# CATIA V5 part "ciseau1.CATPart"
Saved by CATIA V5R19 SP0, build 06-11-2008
Part number: ciseau1
Publications: "D-vis/goupille1"
Bounding box of the stored display mesh (mm): x -136.374 to 15.617, y -131.102 to 16.061, z 0 to 10
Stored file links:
  C:\Documents and Settings\alenoir\Bureau\mécanisme\ciseau1.CATPart
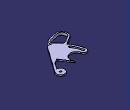
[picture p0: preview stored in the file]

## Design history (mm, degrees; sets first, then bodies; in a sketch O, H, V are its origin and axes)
Parameters
  `D-vis/goupille1` = 30 mm
  LENGTH = 0 mm
Body1 (main body)
  Sketch1 on xy-plane, origin (0.6173, 1.0615, 0), H (0.5482, -0.8363, 0), V (0.8363, 0.5482, 0)
    line L1 (13.9342, 5.5533) -> (55.2099, -98.0146)
    point P1 (16.1474, 0)
    point P2 (0, 200)
    circle A1 centre (0, 0) radius 4
    arc A2 centre (0, 0) radius 125 from (-42.7525, -117.4616) to (9, -124.6756) ccw
    arc A3 centre (42.6692, -103.0126) radius 13.5 from (47.8354, -115.4849) to (55.2099, -98.0146) ccw
    point P4 (47.8354, -115.4849)
    point P8 (0, -30)
    point P9 (0, -22.5)
    arc A4 centre (-27.3616, -75.1754) radius 22.3607 from (-35.0094, -96.1876) to (-27.3616, -52.8147) ccw
    point P10 (-27.3616, -75.1754)
    arc A5 centre (0, 0) radius 15 from (13.9342, 5.5533) to (12.1291, -8.8252) ccw
    line L2 (12.1291, -8.8252) -> (22.1252, -33.907)
    point P13 (22.1252, -52.8147)
    line L3 (-27.3616, -52.8147) -> (22.1252, -52.8147)
    line L4 (22.1252, -52.8147) -> (22.1252, -49.8147)
    line L5 (22.1252, -49.8147) -> (17.1252, -49.8147)
    point P16 (17.1252, -49.8147)
    line L6 (17.1252, -49.8147) -> (22.1252, -47.4832)
    point P17 (22.1252, -47.4832)
    line L7 (22.1252, -47.4832) -> (22.1252, -33.907)
    point P18 (-35.0094, -96.1876)
    spline S1 through (47.8354, -115.4849) (59.6421, -124.3692) (58.5484, -140.7762) (54.1733, -153.5372) (48.7044, -165.9336) (39.5897, -177.6008) (22.8186, -177.9654) (9, -165.7037)
    line L8 (9, -165.7037) -> (9, -124.6756)
    point P19 (9, -165.7037)
    construction line L9 (0, 0) -> (-27.3616, -75.1754)
    arc A6 centre (-38.881, -106.8246) radius 11.3197 from (-42.7525, -117.4616) to (-35.0094, -96.1876) cw
    point P22 (-49.6377, -103.2994)
    construction line L10 (-49.6377, -103.2994) -> (-14.2541, 4.6713)
    point P23 (-14.2541, 4.6713)
    construction line L11 (0, 0) -> (-38.881, -106.8246)
    construction line L12 (0, 0) -> (42.6692, -103.0126)
    axis line L13 (0, 0) -> (0, -125)
    point P24 (0, -125)
    point P25 (47.8354, -115.4849)
    point P26 (9, -165.7037)
    radius A1 = 4
    radius A2 = 125
    radius A3 = 13.5
    radius A4 = 22.3607
    distance P10 O = 80
    distance L2 L1 = 7
    distance P16 L4 = 5
    angle L6 L5 = 25
    distance P13 L1 = 14
    distance L5 L3 = 3
    radius A5 = 15
    angle L13 L12 = 22.5
    angle L11 L13 = 20
    distance L8 L13 = 9
    length L8 = 41.0281
    coincidence: P1 L1, P1 H, P17 L4, L4 L7, P25 P4, P26 P19, A6 P22, P23 A5, P24 A2, P18 L11, P25 L12
    tangency: A3 L1, A3 A2, A5 L1, A4 L3, A6 A2, A6 A4, L10 A5, L10 A6
    horizontal: L3 H
    vertical: L8 V, L13 V, L7 V, L4 V
  Pad1: profile Sketch1, direction (0, 0, 1), length 10
  Sketch2 on start face of Pad1, origin (0.6173, 1.0615, 0), H (0.5482, -0.8363, 0), V (0.8363, 0.5482, 0)
    spline S1 through (14.4994, -165.2858) (23.5036, -173.1647) (37.7673, -172.7797) (45.1958, -161.5242) (49.6979, -150.2687) (53.5247, -137.6625) (54.6502, -125.2814) (44.9707, -121.4545)
    spline S2 through (14.4994, -135.8616) (17.0577, -129.1082) (27.4125, -125.0563)
    line L1 (14.4994, -165.2858) -> (14.4994, -135.8616)
    point P1 (14.4994, -165.2858)
    point P2 (14.4994, -135.8616)
    line L2 (27.4125, -125.0563) -> (44.9707, -121.4545)
    point P3 (27.4125, -125.0563)
    point P4 (44.9707, -121.4545)
    point P5 (14.4994, -165.2858)
    point P6 (14.4994, -135.8616)
    point P7 (27.4125, -125.0563)
    point P8 (44.9707, -121.4545)
    coincidence: P5 P1, P6 P2, P7 P3, P8 P4
    vertical: L1 V
  Pocket1: profile Sketch2, direction (0, 0, 1), through (limit type 6)
  Sketch3 on end face of Pad1, origin (0.6173, 1.0615, 10), H (0.5482, -0.8363, 0), V (0.8363, 0.5482, 0)
    construction arc A1 centre (0, 0) radius 115 from (-39.3323, -108.0647) to (0, -115) ccw
    point P1 (0, -115)
    arc A2 centre (-39.3323, -108.0647) radius 3 from (-40.3584, -110.8837) to (-38.3063, -105.2456) cw
    arc A3 centre (0, -115) radius 3 from (0, -112) to (0, -118) cw
    arc A4 centre (0, 0) radius 112 from (-38.3063, -105.2456) to (0, -112) ccw
    arc A5 centre (0, 0) radius 118 from (0, -118) to (-40.3584, -110.8837) cw
    construction line L1 (0, 0) -> (0, -135.9749)
    point P7 (0, 0)
    axis line L2 (0, 0) -> (-39.3323, -108.0647)
    radius A3 = 3
    radius A1 = 115
    angle L2 L1 = 20
    coincidence: P1 V, P7 V, P7 O
    tangency: A4 A3, A3 A5, A5 A2, A2 A4
    concentricity: A4 O, A5 O
    vertical: L1 V
  Pocket2: profile Sketch3, direction (0, 0, -1), through (limit type 6)
  Sketch4 on start face of Pad1, origin (0.6173, 1.0615, 0), H (0.5482, -0.8363, 0), V (0.8363, 0.5482, 0)
  Sketch5 on start face of Pad1, origin (0.6173, 1.0615, 0), H (0.5482, -0.8363, 0), V (0.8363, 0.5482, 0)
    circle A1 centre (0, 0) radius 125.2848
  Pocket3: profile Sketch5, direction (0, 0, 1), length 5
  Sketch6 on start face of Pad1, origin (0.6173, 1.0615, 0), H (0.5482, -0.8363, 0), V (0.8363, 0.5482, 0)
    circle A1 centre (0, 0) radius 125.3191
  Pocket4: profile Sketch6, direction (0, 0, 1), length 5
  Plane1: stored without definition
  Sketch7 on end face of Pad1, origin (0, 0, 10), H (1, 0, 0), V (0, 1, 0)
    circle A1 centre (0.6173, 1.0615) radius 15
    reference projected arc E1 centre (0.6173, 1.0615) radius 15 from (12.9008, -7.5475) to (-0.1139, -13.9206) ccw from edge [face of Pad1 from Sketch1.A5 | end face of Pad1]
    radius A1 = 15
    concentricity: A1 E1
Current feature: Pocket3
